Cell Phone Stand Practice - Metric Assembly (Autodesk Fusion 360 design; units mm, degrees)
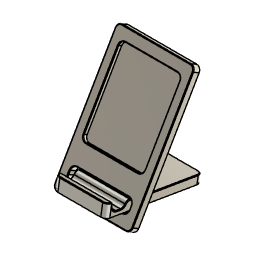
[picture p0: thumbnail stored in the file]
sketch "Main Body Sketch" plane through (0, 0, 0) normal (0, 1, 0) x axis (1, 0, 0)
  line L1 (30, 0) -> (-30, 0)
  line L2 (30, -100) -> (30, 0)
  line L3 (-30, -100) -> (30, -100)
  line L4 (-30, 0) -> (-30, -100)
  line L5 (30, -100) -> (-30, 0)
  line L6 (-30, -100) -> (30, 0)
  line L7 (23.5, -17.5) -> (-23.5, -17.5)
  line L8 (23.5, -8) -> (23.5, -17.5)
  line L9 (-23.5, -8) -> (23.5, -8)
  line L10 (-23.5, -17.5) -> (-23.5, -8)
  line L11 (0, 0) -> (0, -8)
  line L12 (23.5, -92) -> (-23.5, -92)
  line L13 (23.5, -32) -> (23.5, -92)
  line L14 (-23.5, -32) -> (23.5, -32)
  line L15 (-23.5, -92) -> (-23.5, -32)
  line L16 (0, -62.5) -> (0, -50)
  line L17 (17.2022, -62.0451) -> (0, -50)
  line L18 (21, -50) -> (0, -50)
  line L19 (17.2022, -37.9549) -> (0, -50)
  circle C1 centre (0, -50) radius 12.5
  point P6 (0, -50)
  point P1 (0, 0)
  point P11 (0, -8)
  point P12 (0, 0)
  point P17 (0, -50)
  point P21 (0, -50)
  point P22 (0, -62.5)
  point P18 (17.2022, -62.0451)
  point P23 (17.2022, -62.0451)
  point P19 (21, -50)
  point P24 (21, -50)
  point P25 (0, -50)
  point P20 (17.2022, -37.9549)
  point P26 (17.2022, -37.9549)
  point P27 (-17.2022, -62.0451)
  point P28 (-21, -50)
  point P29 (-17.2022, -37.9549)
  point P30 (0, -25)
  point P4 (30, -100)
  point P5 (-30, -100)
  point P3 (30, 0)
  point P8 (23.5, -17.5)
  point P9 (23.5, -8)
  point P7 (-23.5, -17.5)
  point P14 (23.5, -92)
  point P15 (23.5, -32)
  horizontal L1
  perpendicular L1 L2
  parallel L1 L3
  parallel L2 L4
  coincident L5 P6
  coincident L6 P6
  midpoint P1 L1
  horizontal L7
  vertical L8
  horizontal L9
  vertical L10
  midpoint L9 P11
  coincident P1 P12
  vertical L11
  horizontal L12
  vertical L13
  horizontal L14
  vertical L15
  collinear L8 L13
  collinear L10 L15
  coincident P6 P17
  coincident P6 P21
  coincident C1 P22
  vertical L16
  coincident P18 P23
  coincident P19 P24
  perpendicular L16 L18
  coincident P17 P25
  coincident P20 P26
  equal L17 L18
  equal L18 L19
  symmetric P18 L16 P27
  symmetric P19 L16 P28
  symmetric P20 L16 P29
  vertical P6 P30
  dimension "d1" distance P4 P5 = 60
  dimension "d2" distance P3 P4 = 100
  dimension "d3" distance P8 P9 = 9.5
  dimension "d4" distance L1 L9 = 8
  dimension "d5" distance P7 P8 = 47
  dimension "d6" distance L3 L12 = 8 (= "d4")
  dimension "d7" distance P14 P15 = 60
  dimension "d8" diameter C1 = 25
  dimension "d9" distance P21 P24 = 21
  dimension "d10" angle L17 L18 = 35
  dimension "d11" angle L18 L19 = 35 (= "d10")
  dimension "d12" distance P17 P30 = 25
  dimension "d15" R-Pattern1-uDistance = 21
  dimension "d16" R-Pattern1-vDistance = 0
extrude "Extrude1" new body sketch "Main Body Sketch" profile of L1 L2 L3 L4 L7 L8 L9 L10 L12 L13 L14 L15 C1 along normal blind 5.5
extrude "Extrude2" cut sketch "Main Body Sketch" profile of L12 L13 L14 L15 C1 along normal blind 3
fillet "Fillet1" radius 3.5
chamfer "Chamfer1" distance 0.5
move "Move1"
sketch "Stand Body Sketch" plane through (0, 0, 0) normal (1, 0, 0) x axis (0, 1, 0)
  line L1 (14.7999, 15.9408) -> (10.4698, 18.4408)
  line L2 (5.7198, 10.2135) -> (10.0499, 7.7135)
  line L3 (66.5456, 2.9579) -> (12.5794, 12.0948)
  line L4 (66.0448, 0) -> (66.5456, 2.9579)
  line L5 (-7.9029, 12.52) -> (66.0448, 0)
  line L6 (-6.317, 21.8867) -> (-7.9029, 12.52)
  line L7 (-2.3731, 21.2189) -> (-6.317, 21.8867)
  line L8 (-2.3281, 14.6188) -> (-2.3731, 21.2189)
  line L9 (6.5456, 13.1164) -> (-2.3281, 14.6188)
  line L10 (8.7802, 17.0486) -> (6.5456, 13.1164)
  line L11 (16.0467, 18.1003) -> (19.9906, 17.4326)
  line L12 (24.2831, 10.1133) -> (19.9906, 17.4326)
  line L13 (16.0467, 18.1003) -> (12.5794, 12.0948)
  line L14 (54.2999, 84.3568) -> (7.7999, 3.8164)
  line L15 (13.6992, 16.2157) -> (8.7802, 17.0486)
  line L16 (12.1028, 18.768) -> (11.7272, 16.5496)
  line L17 (16.0467, 18.1003) -> (12.1028, 18.768)
  line L18 (15.6711, 15.8819) -> (16.0467, 18.1003)
  line L19 (67.0881, 6.1623) -> (22.1368, 13.7729)
  line L20 (66.5456, 2.9579) -> (67.0881, 6.1623)
  circle C1 centre (13.6992, 16.2157) radius 2
  point P17 (24.2831, 10.1133)
  point P16 (16.0467, 18.1003)
  point P1 (0, 0)
  point P8 (66.0448, 0)
  point P18 (16.0467, 18.1003)
  point P5 (5.7198, 10.2135)
  point P23 (11.7272, 16.5496)
  point P26 (15.6711, 15.8819)
  point P21 (13.6992, 16.2157)
  point P22 (13.6992, 16.2157)
  point P25 (16.0467, 18.1003)
  point P28 (22.1368, 13.7729)
  point P30 (66.5456, 2.9579)
  point P7 (66.5456, 2.9579)
  point P9 (-7.9029, 12.52)
  point P10 (-6.317, 21.8867)
  point P11 (-2.3731, 21.2189)
  point P12 (-2.3281, 14.6188)
  point P13 (6.5456, 13.1164)
  point P15 (19.9906, 17.4326)
  point P14 (8.7802, 17.0486)
  point P27 (6.0499, 0.7853)
  perpendicular L3 L4
  perpendicular L5 L6
  perpendicular L6 L7
  parallel L3 L9
  coincident L3 P17
  collinear L7 L11
  perpendicular L1 L13
  coincident P16 L13
  parallel L3 L5
  horizontal P1 P8
  collinear L3 L9
  coincident P16 P18
  collinear L13 L14
  coincident P5 L5
  parallel L5 L15
  coincident C1 P23
  perpendicular L16 L17
  coincident C1 P26
  tangent C1 L18
  perpendicular L17 L18
  tangent C1 L16
  parallel L6 L16
  coincident P21 P22
  collinear L11 L17
  coincident P18 P25
  midpoint L12 P28
  perpendicular L4 L19
  coincident L3 P30
  perpendicular L3 L20
  coincident P7 P30
  dimension "d30" distance P8 P9 = 75
  dimension "d31" distance P7 P8 = 3
  dimension "d32" distance P9 P10 = 9.5
  dimension "d33" angle L11 L12 = 50
  dimension "d34" distance P10 P11 = 4
  dimension "d35" distance P12 P13 = 9
  dimension "d36" distance P15 P16 = 4
  dimension "d37" distance L9 P14 = 4.25
  dimension "d38" angle L9 L10 = 70
  dimension "d39" angle L8 L9 = 100
  dimension "d40" diameter C1 = 4
  dimension "d41" distance P8 P27 = 60
extrude "Extrude3" new body sketch "Stand Body Sketch" profile of L3 L4 L5 L6 L7 L8 L9 L10 L11 L12 L13 L14 L15 C1 L18 L19 L20 distance 40
fillet "Fillet2" radius 3.5
chamfer "Chamfer2" distance 0.5
named bodies: "Main Body", "Stand Body"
